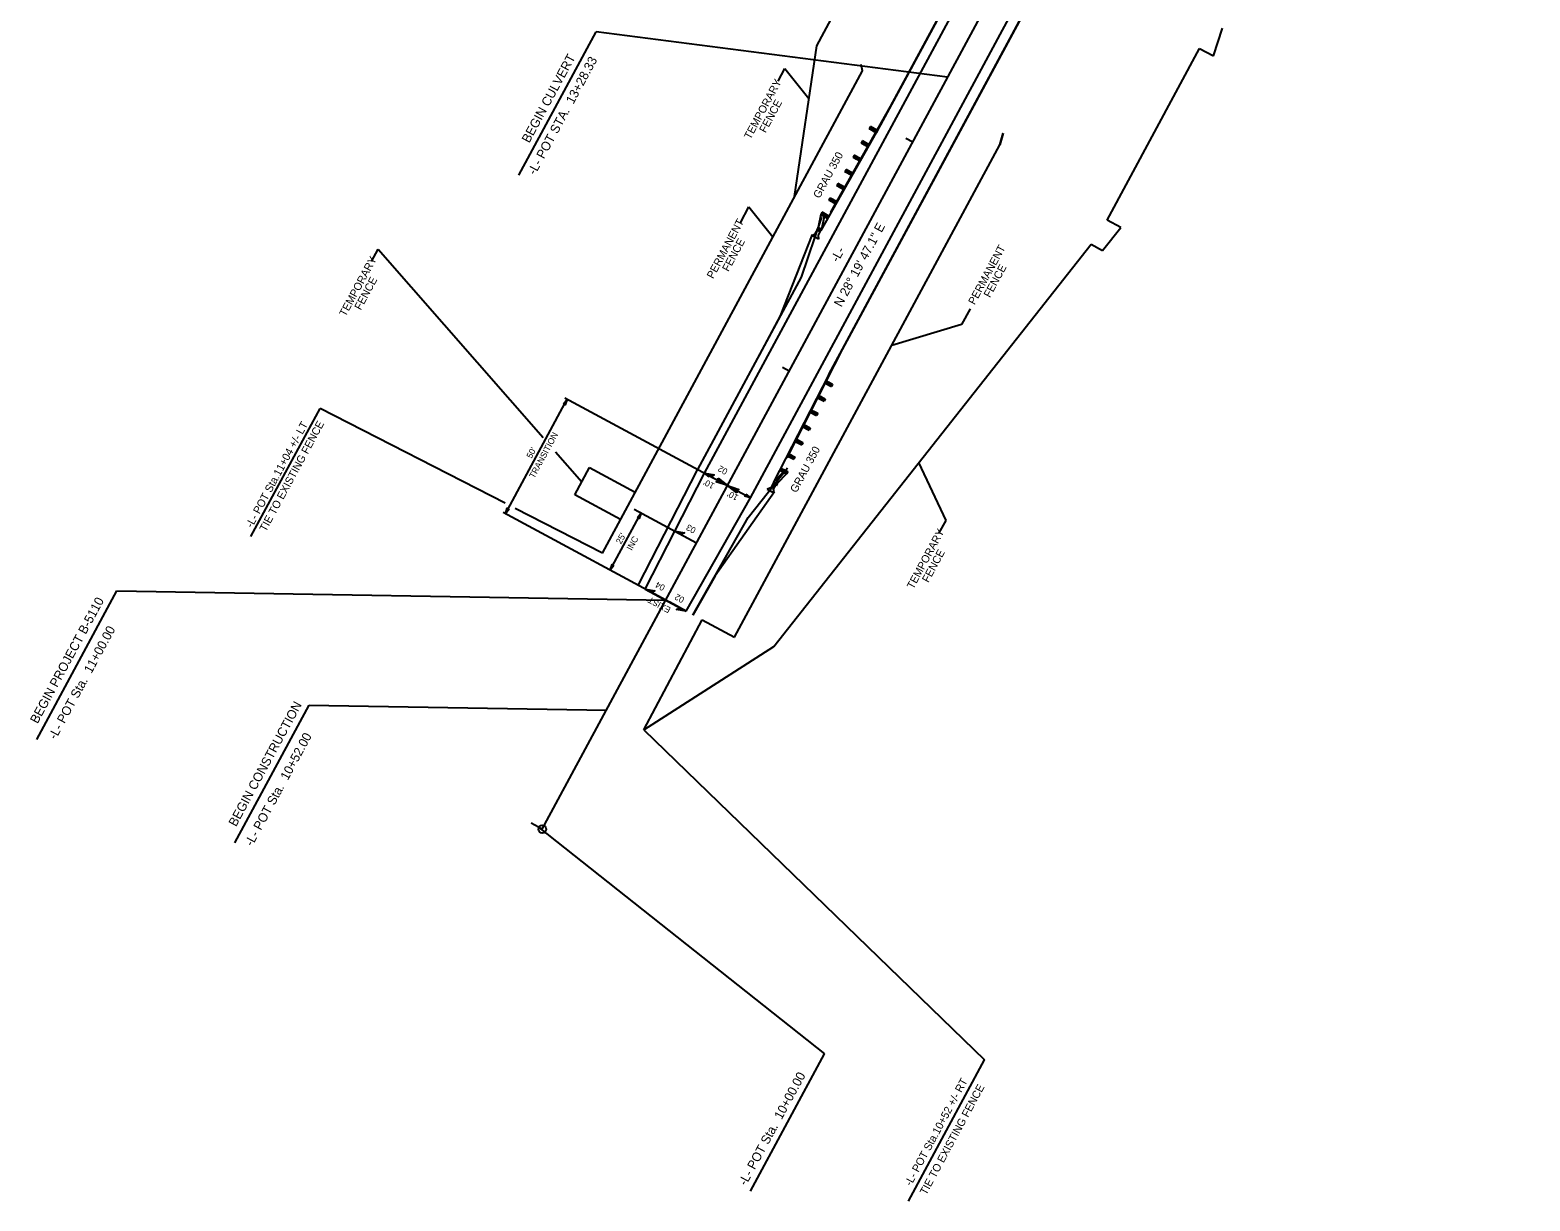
# Model space of a CAD drawing. Extents: x 1376855 to 1377489, y 762573 to 763464.
# Drawn here: x 1376855 to 1377431, y 762573 to 763023 of the extents above; entities that cross this region are included whole.
import ezdxf

# ---------------------------------------------------------------- set-up
doc = ezdxf.new("R2010")
doc.units = 0
for name, color, linetype in [('Prop Dimension', 7, 'Continuous'), ('Prop Dimension Text', 7, 'Continuous'), ('Prop EOT', 7, 'Continuous'), ('Prop Fence Barbed Wire', 7, 'Continuous'), ('Prop Guardrail Anchor Unit CELL', 7, 'Continuous'), ('Prop Horizontal Alignment', 7, 'Continuous'), ('Prop Horizontal Alignment Direction Label', 7, 'Continuous'), ('Prop Horizontal Alignment Station Label', 7, 'Continuous'), ('Prop Horizontal Alignment Tick Large', 7, 'Continuous'), ('Prop Horizontal Alignment Tick Small', 7, 'Continuous'), ('Prop Superelevation  Arrow CELL', 7, 'Continuous'), ('Prop Terminator CELL', 7, 'Continuous'), ('Scratch_Level_1', 7, 'Continuous'), ('Scratch_Level_2', 7, 'Continuous'), ('Scratch_Level_6', 7, 'Continuous')]:
    doc.layers.add(name, color=color, linetype=linetype)

msp = doc.modelspace()

# ---------------------------------------------------------------- linework, layer by layer
at = {"layer": 'Prop Dimension'}
for p, q in [((1377142.48, 763003.15), (1377145.06, 763007.93)), ((1377145.06, 763007.93), (1377154.28, 762996.42)), ((1377127.92, 762948.7), (1377131.2, 762954.79)), ((1377131.2, 762954.79), (1377140.42, 762943.28)), ((1376986.12, 762933.83), (1376988.7, 762938.61)), ((1376988.7, 762938.61), (1377052.08, 762866.11)), ((1377216.23, 762915.63), (1377212.95, 762909.55)), ((1377212.95, 762909.55), (1377186.1, 762901.58)), ((1376939.78, 762828.1), (1376966.34, 762877.35)), ((1377037.48, 762840.93), (1376966.34, 762877.35)), ((1377037.61, 762836.87), (1377061.34, 762880.89)), ((1377060.46, 762881.36), (1377131.76, 762842.92)), ((1377056.88, 762860.61), (1377066.93, 762849.11)), ((1377206.95, 762834.26), (1377196.56, 762856.58)), ((1377107.07, 762799.43), (1377036.73, 762837.35)), ((1377074.91, 762821.77), (1377041.4, 762838.92)), ((1377204.37, 762829.48), (1377206.95, 762834.26)), ((1376857.47, 762750.13), (1376888.25, 762807.24)), ((1376888.25, 762807.24), (1377099.23, 762803.66)), ((1376933.66, 762710.38), (1376962.22, 762763.34)), ((1376962.22, 762763.34), (1377076.45, 762761.4)), ((1377090.8, 762753.87), (1377221.78, 762627.04)), ((1377192.5, 762572.74), (1377221.78, 762627.04))]:
    msp.add_line(p, q, dxfattribs=at)
at = {"layer": 'Prop Dimension Text'}
for points in [[(1377119.36, 762850.48), (1377122.95, 762847.67), (1377118.59, 762849.11), (1377119.48, 762849.54)], [(1377126.55, 762844.85), (1377122.95, 762847.67), (1377127.32, 762846.22), (1377126.43, 762845.79)]]:
    msp.add_lwpolyline(points, close=True, dxfattribs=at)
at = {"layer": 'Prop EOT'}
for p, q in [((1377114.15, 762852.41), (1377303.97, 763204.51)), ((1377131.76, 762842.92), (1377321.57, 763195.01)), ((1377091.33, 762807.91), (1377114.15, 762852.41)), ((1377107.07, 762799.43), (1377131.76, 762842.92))]:
    msp.add_line(p, q, dxfattribs=at)
at = {"layer": 'Prop Fence Barbed Wire'}
for p, q in [((1377268.17, 763146.53), (1377181.82, 762986.36)), ((1377157.24, 763016.63), (1377185.72, 763069.45)), ((1377161.86, 762890.33), (1377248.21, 763050.51)), ((1377309.7, 763012.83), (1377313.16, 763023.46)), ((1377148.75, 762958.73), (1377157.24, 763016.63)), ((1377268.83, 762949.66), (1377304.42, 763015.68)), ((1377304.42, 763015.68), (1377309.7, 763012.83)), ((1377228.9, 762983.18), (1377227.66, 762978.67)), ((1377227.66, 762978.67), (1377228.9, 762983.18)), ((1377125.63, 762789.42), (1377227.66, 762978.67)), ((1377267.13, 762938.08), (1377274.11, 762946.81)), ((1377274.11, 762946.81), (1377268.83, 762949.66)), ((1377140.74, 762785.82), (1377262.73, 762940.45)), ((1377262.73, 762940.45), (1377267.13, 762938.08)), ((1377064.23, 762844.11), (1377069.93, 762854.67)), ((1377069.93, 762854.67), (1377087.53, 762845.18)), ((1377081.84, 762834.62), (1377064.23, 762844.11)), ((1377090.8, 762753.87), (1377113.17, 762796.14)), ((1377113.17, 762796.14), (1377125.63, 762789.42)), ((1377090.8, 762753.87), (1377140.74, 762785.82))]:
    msp.add_line(p, q, dxfattribs=at)
msp.add_lwpolyline([(1377074.91, 762821.77), (1377174.85, 763007.14), (1377174.33, 763009.57)], dxfattribs=at)
at = {"layer": 'Prop Guardrail Anchor Unit CELL'}
for p, q in [((1377181.81, 762986.36), (1377158.81, 762945.66)), ((1377177.95, 762985.63), (1377177.46, 762984.76)), ((1377177.46, 762984.76), (1377179.25, 762984.89)), ((1377180.07, 762983.28), (1377177.46, 762984.76)), ((1377180.56, 762984.15), (1377177.95, 762985.63)), ((1377178.76, 762984.02), (1377177.95, 762985.63)), ((1377179.25, 762984.89), (1377178.76, 762984.02)), ((1377178.76, 762984.02), (1377180.56, 762984.15)), ((1377180.07, 762983.28), (1377178.76, 762984.02)), ((1377179.25, 762984.89), (1377180.07, 762983.28)), ((1377180.56, 762984.15), (1377180.07, 762983.28)), ((1377171.71, 762974.68), (1377171.21, 762973.81)), ((1377174.36, 762973.18), (1377171.71, 762974.68)), ((1377172.54, 762973.06), (1377171.71, 762974.68)), ((1377174.8, 762980.17), (1377174.31, 762979.3)), ((1377174.31, 762979.3), (1377176.13, 762979.42)), ((1377176.97, 762977.79), (1377174.31, 762979.3)), ((1377177.46, 762978.66), (1377174.8, 762980.17)), ((1377175.64, 762978.54), (1377174.8, 762980.17)), ((1377176.13, 762979.42), (1377175.64, 762978.54)), ((1377177.46, 762978.66), (1377175.64, 762978.54)), ((1377176.13, 762979.42), (1377176.97, 762977.79)), ((1377168.62, 762969.19), (1377168.12, 762968.32)), ((1377171.26, 762967.69), (1377168.62, 762969.19)), ((1377169.44, 762967.57), (1377168.62, 762969.19)), ((1377171.21, 762973.81), (1377173.03, 762973.93)), ((1377173.87, 762972.31), (1377171.21, 762973.81)), ((1377173.03, 762973.93), (1377172.54, 762973.06)), ((1377174.36, 762973.18), (1377172.54, 762973.06)), ((1377173.03, 762973.93), (1377173.87, 762972.31)), ((1377165.43, 762963.75), (1377164.93, 762962.88)), ((1377164.93, 762962.88), (1377166.79, 762962.98)), ((1377168.16, 762962.21), (1377165.43, 762963.75)), ((1377166.3, 762962.11), (1377165.43, 762963.75)), ((1377166.79, 762962.98), (1377166.3, 762962.11)), ((1377166.79, 762962.98), (1377167.67, 762961.34)), ((1377168.12, 762968.32), (1377169.94, 762968.44)), ((1377170.77, 762966.82), (1377168.12, 762968.32)), ((1377169.94, 762968.44), (1377169.44, 762967.57)), ((1377171.26, 762967.69), (1377169.44, 762967.57)), ((1377169.94, 762968.44), (1377170.77, 762966.82)), ((1377171.26, 762967.69), (1377170.77, 762966.82)), ((1377162.45, 762958.2), (1377161.95, 762957.33)), ((1377161.95, 762957.33), (1377163.75, 762957.46)), ((1377164.56, 762955.85), (1377161.95, 762957.33)), ((1377165.06, 762956.72), (1377162.45, 762958.2)), ((1377163.26, 762956.59), (1377162.45, 762958.2)), ((1377163.75, 762957.46), (1377163.26, 762956.59)), ((1377163.75, 762957.46), (1377164.56, 762955.85)), ((1377167.67, 762961.34), (1377164.93, 762962.88)), ((1377168.16, 762962.21), (1377166.3, 762962.11)), ((1377158.8, 762951.87), (1377157.75, 762946.84)), ((1377159.29, 762952.74), (1377158.8, 762951.87)), ((1377158.8, 762951.87), (1377160.62, 762951.99)), ((1377161.46, 762950.37), (1377158.8, 762951.87)), ((1377161.96, 762951.24), (1377159.29, 762952.74)), ((1377160.13, 762951.12), (1377159.29, 762952.74)), ((1377160.62, 762951.99), (1377160.13, 762951.12)), ((1377160.62, 762951.99), (1377161.46, 762950.37)), ((1377165.06, 762956.72), (1377163.26, 762956.59)), ((1377156.68, 762944.46), (1377157.65, 762946.26)), ((1377157.75, 762946.84), (1377157.25, 762945.97)), ((1377157.25, 762945.97), (1377159.05, 762946.1)), ((1377158.56, 762945.23), (1377157.25, 762945.97)), ((1377157.75, 762946.84), (1377157.5, 762946.4)), ((1377157.65, 762946.26), (1377158.19, 762945.96)), ((1377159.05, 762946.1), (1377157.75, 762946.84)), ((1377158.56, 762945.23), (1377157.75, 762946.84)), ((1377158.19, 762945.96), (1377158.72, 762945.67)), ((1377160.13, 762951.12), (1377159.05, 762946.1)), ((1377161.96, 762951.24), (1377160.13, 762951.12)), ((1377155.36, 762943.83), (1377156.68, 762944.46)), ((1377157.95, 762942.43), (1377155.36, 762943.83)), ((1377158.72, 762945.67), (1377157.75, 762943.87)), ((1377157.75, 762943.87), (1377157.95, 762942.43)), ((1377161.86, 762890.33), (1377140.5, 762848.74)), ((1377160.7, 762888.07), (1377160.24, 762887.18)), ((1377160.7, 762888.07), (1377163.37, 762886.7)), ((1377161.58, 762886.49), (1377160.7, 762888.07)), ((1377157.82, 762882.46), (1377160.53, 762881.07)), ((1377157.82, 762882.46), (1377158.72, 762880.88)), ((1377162.03, 762887.38), (1377160.24, 762887.18)), ((1377160.24, 762887.18), (1377162.91, 762885.81)), ((1377160.24, 762887.18), (1377161.58, 762886.49)), ((1377162.03, 762887.38), (1377161.58, 762886.49)), ((1377161.58, 762886.49), (1377163.37, 762886.7)), ((1377162.91, 762885.81), (1377162.03, 762887.38)), ((1377163.37, 762886.7), (1377162.91, 762885.81)), ((1377154.94, 762876.86), (1377157.65, 762875.47)), ((1377154.94, 762876.86), (1377155.84, 762875.27)), ((1377159.18, 762881.77), (1377157.36, 762881.57)), ((1377157.36, 762881.57), (1377160.08, 762880.18)), ((1377159.18, 762881.77), (1377158.72, 762880.88)), ((1377158.72, 762880.88), (1377160.53, 762881.07)), ((1377160.08, 762880.18), (1377159.18, 762881.77)), ((1377160.53, 762881.07), (1377160.08, 762880.18)), ((1377152.06, 762871.25), (1377151.6, 762870.36)), ((1377152.06, 762871.25), (1377154.76, 762869.87)), ((1377152.06, 762871.25), (1377152.96, 762869.67)), ((1377156.3, 762876.16), (1377154.48, 762875.97)), ((1377154.48, 762875.97), (1377157.19, 762874.58)), ((1377156.3, 762876.16), (1377155.84, 762875.27)), ((1377155.84, 762875.27), (1377157.65, 762875.47)), ((1377157.19, 762874.58), (1377156.3, 762876.16)), ((1377157.65, 762875.47), (1377157.19, 762874.58)), ((1377149.18, 762865.65), (1377151.97, 762864.21)), ((1377149.18, 762865.65), (1377150.12, 762864.04)), ((1377153.41, 762870.56), (1377151.6, 762870.36)), ((1377151.6, 762870.36), (1377154.31, 762868.98)), ((1377153.41, 762870.56), (1377152.96, 762869.67)), ((1377152.96, 762869.67), (1377154.76, 762869.87)), ((1377154.31, 762868.98), (1377153.41, 762870.56)), ((1377154.76, 762869.87), (1377154.31, 762868.98)), ((1377147.64, 762859.36), (1377145.85, 762859.15)), ((1377146.3, 762860.04), (1377148.97, 762858.67)), ((1377146.3, 762860.04), (1377147.18, 762858.47)), ((1377147.64, 762859.36), (1377147.18, 762858.47)), ((1377148.52, 762857.78), (1377147.64, 762859.36)), ((1377150.58, 762864.93), (1377148.73, 762864.76)), ((1377148.73, 762864.76), (1377151.52, 762863.32)), ((1377150.58, 762864.93), (1377150.12, 762864.04)), ((1377150.12, 762864.04), (1377151.97, 762864.21)), ((1377151.52, 762863.32), (1377150.58, 762864.93)), ((1377151.97, 762864.21), (1377151.52, 762863.32)), ((1377144.79, 762853.74), (1377142.97, 762853.55)), ((1377142.97, 762853.55), (1377145.69, 762852.15)), ((1377143.43, 762854.44), (1377146.15, 762853.04)), ((1377143.43, 762854.44), (1377144.33, 762852.85)), ((1377144.79, 762853.74), (1377144.33, 762852.85)), ((1377145.69, 762852.15), (1377144.79, 762853.74)), ((1377145.85, 762859.15), (1377148.52, 762857.78)), ((1377147.18, 762858.47), (1377148.97, 762858.67)), ((1377148.97, 762858.67), (1377148.52, 762857.78)), ((1377140.55, 762848.68), (1377139.59, 762846.88)), ((1377140.27, 762848.3), (1377142.06, 762848.5)), ((1377140.27, 762848.3), (1377141.61, 762847.61)), ((1377141.09, 762848.39), (1377140.55, 762848.68)), ((1377140.66, 762846.3), (1377141.63, 762848.1)), ((1377144.33, 762852.85), (1377140.73, 762849.19)), ((1377140.73, 762849.19), (1377142.06, 762848.5)), ((1377141.61, 762847.61), (1377140.73, 762849.19)), ((1377141.63, 762848.1), (1377141.09, 762848.39)), ((1377142.06, 762848.5), (1377141.61, 762847.61)), ((1377142.06, 762848.5), (1377141.84, 762848.06)), ((1377145.69, 762852.15), (1377142.06, 762848.5)), ((1377144.33, 762852.85), (1377146.15, 762853.04)), ((1377146.15, 762853.04), (1377145.69, 762852.15)), ((1377139.59, 762846.88), (1377138.27, 762846.25)), ((1377138.27, 762846.25), (1377140.86, 762844.86)), ((1377140.86, 762844.86), (1377140.66, 762846.3))]:
    msp.add_line(p, q, dxfattribs=at)
at = {"layer": 'Prop Horizontal Alignment'}
msp.add_line((1377051.77, 762715.63), (1377431.41, 763419.82), dxfattribs=at)
at = {"layer": 'Prop Horizontal Alignment Station Label'}
for p, q in [((1377042.79, 762966.95), (1377072.51, 763022.09)), ((1377207.58, 763004.64), (1377072.51, 763022.09)), ((1377050.45, 762716.34), (1377160.2, 762629.27)), ((1377131.77, 762576.53), (1377160.2, 762629.27))]:
    msp.add_line(p, q, dxfattribs=at)
msp.add_circle((1377051.77, 762715.63), 1.5, dxfattribs=at)
at = {"layer": 'Prop Horizontal Alignment Tick Large'}
msp.add_line((1377051.77, 762715.63), (1377047.55, 762717.91), dxfattribs=at)
at = {"layer": 'Prop Horizontal Alignment Tick Small'}
for p, q in [((1377194.14, 762979.7), (1377191.5, 762981.13)), ((1377146.68, 762891.68), (1377144.04, 762893.1)), ((1377099.23, 762803.66), (1377094.83, 762806.03))]:
    msp.add_line(p, q, dxfattribs=at)
at = {"layer": 'Prop Superelevation  Arrow CELL'}
for p, q in [((1377114.15, 762852.41), (1377122.95, 762847.67)), ((1377114.15, 762852.41), (1377122.95, 762847.67)), ((1377077.88, 762815.16), (1377089.75, 762837.17)), ((1377087.03, 762838.63), (1377111.09, 762825.66)), ((1377102.74, 762830.16), (1377111.09, 762825.66)), ((1377091.33, 762807.91), (1377107.07, 762799.43)), ((1377091.33, 762807.91), (1377097.67, 762804.5)), ((1377107.07, 762799.43), (1377100.74, 762802.84))]:
    msp.add_line(p, q, dxfattribs=at)
for points in [[(1377114.15, 762852.41), (1377117.89, 762851.76), (1377116.59, 762851.1)], [(1377102.74, 762830.16), (1377106.48, 762829.51), (1377105.18, 762828.85)], [(1377091.33, 762807.91), (1377095.07, 762807.26), (1377093.77, 762806.6)], [(1377107.07, 762799.43), (1377103.34, 762800.08), (1377104.63, 762800.74)]]:
    msp.add_lwpolyline(points, close=True, dxfattribs=at)
at = {"layer": 'Prop Terminator CELL'}
for points in [[(1377059.93, 762879.09), (1377061.34, 762880.89), (1377060.62, 762878.7), (1377060.4, 762879.15)], [(1377115.95, 762851), (1377114.15, 762852.41), (1377116.33, 762851.69), (1377115.89, 762851.48)], [(1377129.96, 762844.33), (1377131.76, 762842.92), (1377129.58, 762843.64), (1377130.02, 762843.86)], [(1377039.02, 762838.67), (1377037.61, 762836.87), (1377038.33, 762839.06), (1377038.55, 762838.61)], [(1377088.34, 762835.37), (1377089.75, 762837.17), (1377089.02, 762834.99), (1377088.81, 762835.43)], [(1377079.29, 762816.96), (1377077.88, 762815.16), (1377078.6, 762817.34), (1377078.82, 762816.9)]]:
    msp.add_lwpolyline(points, close=True, dxfattribs=at)
at = {"layer": 'Scratch_Level_1'}
for p, q in [((1377185.63, 762993.43), (1377268.65, 763147.43)), ((1377249.93, 763053.68), (1377167.07, 762900)), ((1377162.63, 762952.73), (1377185.63, 762993.43)), ((1377167.07, 762900), (1377145.71, 762858.41))]:
    msp.add_line(p, q, dxfattribs=at)
at = {"layer": 'Scratch_Level_2'}
for p, q in [((1377151.4, 762927.82), (1377159.26, 762950.84)), ((1377111.51, 762853.84), (1377151.4, 762927.82)), ((1377088.66, 762809.28), (1377111.48, 762853.78)), ((1377130.94, 762835.41), (1377145.99, 762854.57)), ((1377109.68, 762797.94), (1377130.94, 762835.41))]:
    msp.add_line(p, q, dxfattribs=at)
at = {"layer": 'Scratch_Level_6'}
for p, q in [((1377143.39, 762912.96), (1377155.68, 762944.2)), ((1377135.24, 762897.85), (1377143.39, 762912.96)), ((1377141, 762845.32), (1377118.23, 762813.01)), ((1377118.23, 762813.01), (1377109.68, 762797.94))]:
    msp.add_line(p, q, dxfattribs=at)

# ---------------------------------------------------------------- texts
at = {"layer": 'Prop Dimension Text'}
for s, height, rotation, p in [('TEMPORARY', 3, 61.67024, (1377131.78, 762980.49)), ('FENCE', 3, 61.67024, (1377137.6, 762983.01)), ('PERMANENT', 3, 61.67024, (1377117.43, 762926.95)), ('FENCE', 3, 61.67024, (1377123.37, 762929.67)), ('PERMANENT', 3, 61.67024, (1377217.94, 762916.94)), ('TEMPORARY', 3, 61.67024, (1376976.19, 762912.38)), ('FENCE', 3, 61.67024, (1377223.87, 762919.67)), ('FENCE', 3, 61.67024, (1376982.01, 762914.89)), ('-L- POT Sta.11+04 +/- LT', 3, 61.67024, (1376940.24, 762831.22)), ('TIE TO EXISTING FENCE', 3, 61.67024, (1376945.53, 762829.73)), ('TRANSITION', 2.4, 61.67024, (1377048.72, 762850.24)), ("50'", 2.4, 61.67024, (1377047.65, 762857.88)), ("10'", 2.4, 151.67024, (1377118.24, 762848.31)), ("10'", 2.4, 151.67024, (1377127.4, 762843.82)), ('TEMPORARY', 3, 61.67024, (1377194.36, 762807.65)), ("25'", 2.4, 61.67024, (1377082.02, 762824.97)), ('INC', 2.4, 61.67024, (1377086.18, 762822.52)), ('FENCE', 3, 61.67024, (1377200.19, 762810.16)), ('BEGIN PROJECT B-5110', 3.5, 61.67024, (1376857.77, 762755.94)), ('EXIST', 2.4, 151.67024, (1377101.39, 762800.65)), ('-L- POT Sta.  11+00.00', 3.5, 61.67024, (1376864.78, 762749.82)), ('BEGIN CONSTRUCTION', 3.5, 61.67024, (1376934.06, 762716.37)), ('-L- POT Sta.  10+52.00', 3.5, 61.67024, (1376940.28, 762708.78)), ('-L- POT Sta.10+52 +/- RT', 3, 61.67024, (1377193.49, 762578.25)), ('TIE TO EXISTING FENCE', 3, 61.67024, (1377199.34, 762574.81))]:
    msp.add_text(s, height=height, rotation=rotation, dxfattribs=at).set_placement(p)
at = {"layer": 'Prop Guardrail Anchor Unit CELL'}
for p in [(1377158.34, 762957.8), (1377149.48, 762844.67)]:
    msp.add_text('GRAU 350', height=3, rotation=61.67024, dxfattribs=at).set_placement(p)
at = {"layer": 'Prop Horizontal Alignment Direction Label'}
for s, p in [('N 28%%d 19\' 47.1" E', (1377166.74, 762916.05)), ('-L-', (1377165.47, 762933.23))]:
    msp.add_text(s, height=3.5, rotation=61.67024, dxfattribs=at).set_placement(p)
at = {"layer": 'Prop Horizontal Alignment Station Label'}
for s, p in [('BEGIN CULVERT', (1377046.74, 762979.1)), ('-L- POT STA.  13+28.33', (1377049.03, 762966.82)), ('-L- POT Sta.  10+00.00', (1377130.07, 762578.37))]:
    msp.add_text(s, height=3.5, rotation=61.67024, dxfattribs=at).set_placement(p)
at = {"layer": 'Prop Superelevation  Arrow CELL'}
for s, p in [('02', (1377123.27, 762853.81)), ('03', (1377111.07, 762831.23)), ('04', (1377099.2, 762809.17)), ('02', (1377106.63, 762804.52))]:
    msp.add_text(s, height=2.4, rotation=151.67024, dxfattribs=at).set_placement(p)

doc.saveas('drawing.dxf')
